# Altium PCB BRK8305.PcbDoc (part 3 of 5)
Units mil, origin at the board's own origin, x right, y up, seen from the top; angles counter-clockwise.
Board outline 5944.89 x 4139.76 mil, 4 copper layers (L1-Top, L2-GND, L3-GND, L4-BOT), stack 61.2 mil thick; 237 components, 286 nets, 1257 pads, 698 vias.
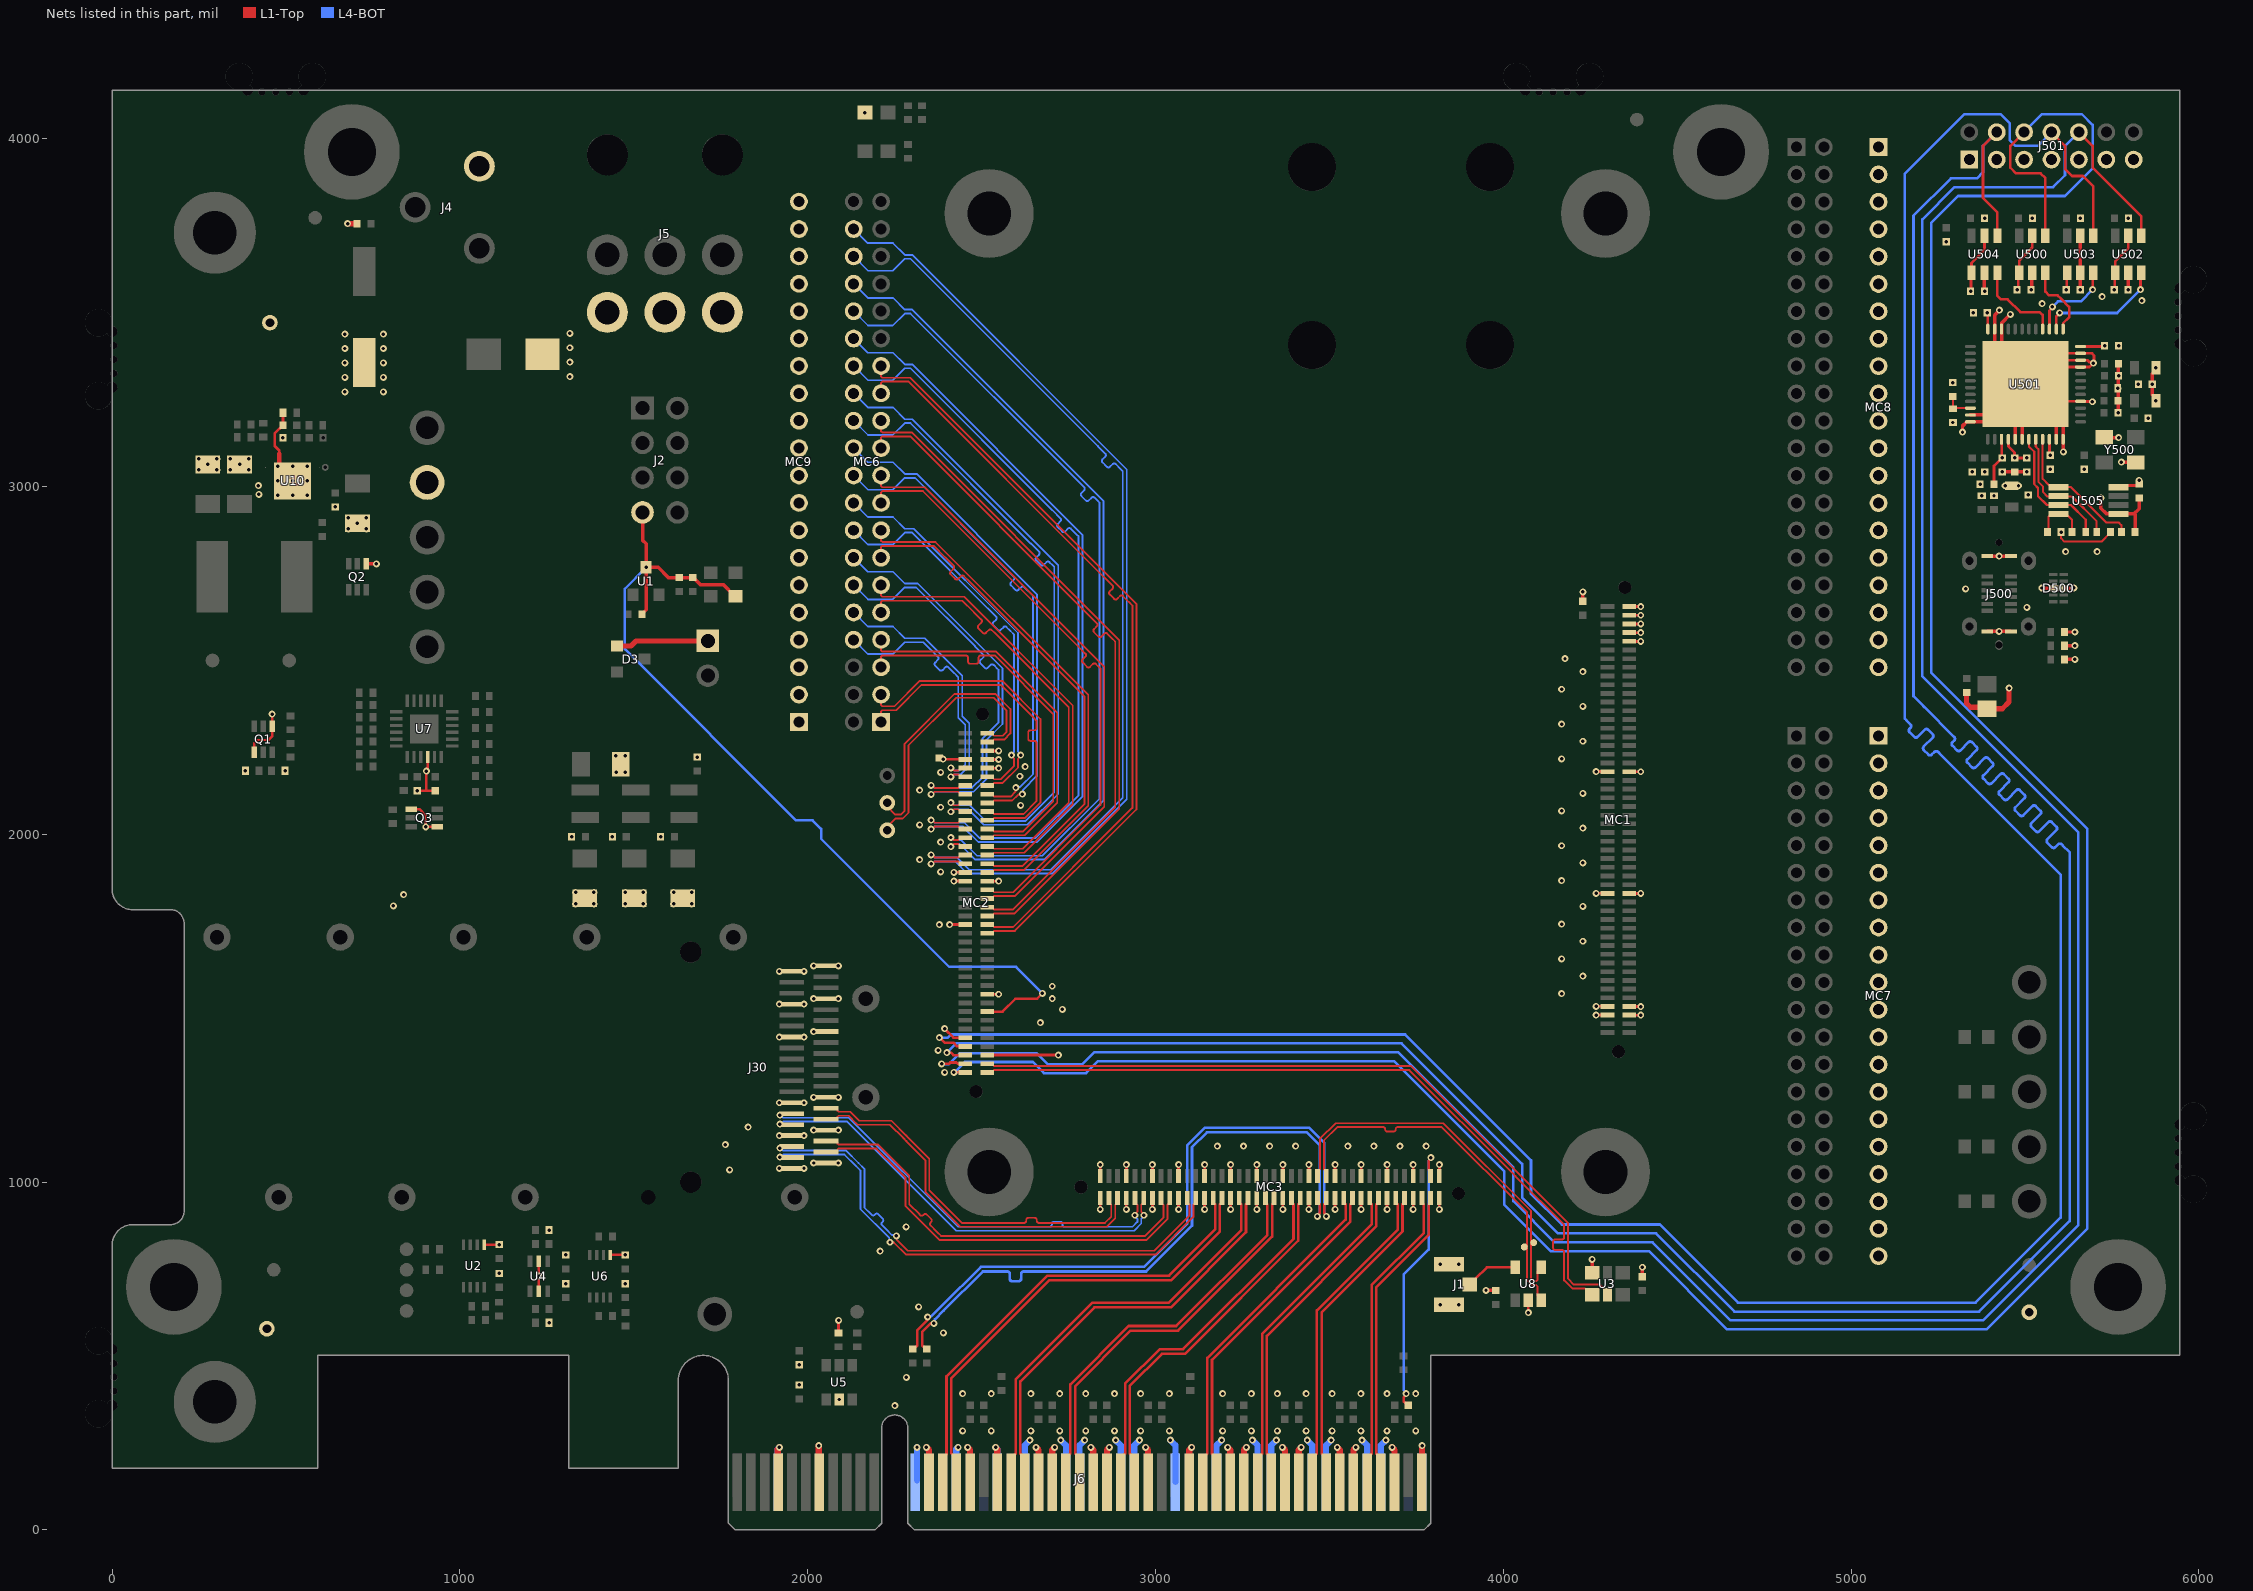
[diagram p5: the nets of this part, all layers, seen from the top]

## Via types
v1: diameter 20, hole 10, L1-Top to L4-BOT, tented both sides, 698 vias

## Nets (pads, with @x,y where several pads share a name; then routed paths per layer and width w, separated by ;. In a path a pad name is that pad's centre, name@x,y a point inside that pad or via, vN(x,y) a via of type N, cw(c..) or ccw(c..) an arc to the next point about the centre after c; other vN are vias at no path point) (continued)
B85_L10N: MC2.36 MC6.25 | length 2202.8
  L1-Top w5.25: MC6.25@2210.82,3268.11 2210.82,3298.78 2213.89,3301.86 2289.75,3301.86 2853.01,2738.6 2854.86,2736.74 2876.25,2715.35 cw(c2871.98,2711.07) 2876.25,2706.79 2867.96,2698.5 ccw(c2872.23,2694.22) 2867.96,2689.94 2880.79,2677.11 ccw(c2885.07,2681.39) 2889.35,2677.11 2897.64,2685.4 cw(c2901.92,2681.13) 2906.2,2685.4 2923.61,2668 2925.46,2666.14 2933.42,2658.18 2933.42,2076.24 2590.85,1733.68 2535.42,1733.68 2528.54,1740.55 MC2.36@2515.75,1740.55
B85_L10P: MC2.34 MC6.27 | length 2202.8
  L1-Top w5.25: MC6.27@2210.82,3346.85 2210.82,3316.18 2213.89,3313.11 2294.41,3313.11 2941.37,2666.14 2944.67,2662.84 2944.67,2071.58 2595.51,1722.43 2535.42,1722.43 2528.54,1715.55 MC2.34@2515.75,1715.55
B85_L11N: MC2.40 MC6.21 | length 1956.2
  L1-Top w5.25: MC6.21@2210.82,3110.63 2210.82,3141.3 2213.89,3144.37 2294.03,3144.37 2808.04,2630.37 2809.89,2628.51 2831.28,2607.12 cw(c2827,2602.85) 2831.28,2598.57 2822.99,2590.27 ccw(c2827.26,2585.99) 2822.99,2581.72 2835.82,2568.88 ccw(c2840.1,2573.16) 2844.38,2568.88 2852.67,2577.18 cw(c2856.95,2572.9) 2861.23,2577.18 2877.1,2561.3 2878.96,2559.45 2884.26,2554.14 2884.26,2078.59 2589.35,1783.68 2535.42,1783.68 2528.54,1790.55 MC2.40@2515.75,1790.55
B85_L11P: MC2.38 MC6.23 | length 1956.2
  L1-Top w5.25: MC6.23@2210.82,3189.37 2210.82,3158.7 2213.89,3155.62 2298.69,3155.62 2895.51,2558.8 2895.51,2073.93 2594.01,1772.43 2535.42,1772.43 2528.54,1765.55 MC2.38@2515.75,1765.55
B85_L12N: MC2.44 MC6.17 | length 1735.7
  L1-Top w5.25: MC6.17@2210.82,2953.15 2210.82,2983.82 2213.89,2986.89 2218.55,2986.89 2331.35,2986.89 2775.1,2543.15 2776.96,2541.29 2798.35,2519.9 cw(c2794.07,2515.62) 2798.35,2511.34 2790.05,2503.05 ccw(c2794.33,2498.77) 2790.05,2494.49 2802.89,2481.66 ccw(c2807.17,2485.93) 2811.44,2481.66 2819.74,2489.95 cw(c2824.02,2485.67) 2828.3,2489.95 2834.79,2483.46 2836.65,2481.6 2841.31,2476.94 2841.31,2084.42 2590.56,1833.68 2535.42,1833.68 2528.54,1840.55 MC2.44@2515.75,1840.55
B85_L12P: MC2.42 MC6.19 | length 1735.7
  L1-Top w5.25: MC6.19@2210.82,3031.89 2210.82,3001.22 2213.89,2998.14 2336.01,2998.14 2852.56,2481.6 2852.56,2079.76 2595.22,1822.43 2535.42,1822.43 2528.54,1815.55 MC2.42@2515.75,1815.55
B86_L1N: MC2.71 MC6.8 | length 768.7
  L1-Top w5.25: v1(2411.42,2191.05) 2412.87,2191.05 2420.24,2183.68 2433.09,2183.68 2439.96,2190.55 MC2.71@2452.76,2190.55
  L4-BOT w5.25: MC6.8@2132.08,2559.45 2173.18,2518.35 2244.52,2518.35 2278.85,2552.67 2332.19,2552.67 2351.02,2533.84 2352.88,2531.99 2374.27,2510.6 cw(c2369.99,2506.32) 2374.27,2502.04 2366.14,2493.91 ccw(c2370.42,2489.63) 2366.14,2485.36 2378.98,2472.52 ccw(c2383.26,2476.8) 2387.53,2472.52 2395.66,2480.65 cw(c2399.94,2476.37) 2404.22,2480.65 2418.54,2466.33 2420.4,2464.47 2432.79,2452.08 2432.79,2334.81 2452.76,2314.84 2452.76,2200.79 2435.64,2183.68 2421.87,2183.68 2414.49,2191.05 v1(2411.42,2191.05)
B86_L1P: MC2.69 MC6.10 | length 768.7
  L1-Top w5.25: v1(2411.42,2165.05) 2412.87,2165.05 2420.24,2172.43 2433.09,2172.43 2439.96,2165.55 MC2.69@2452.76,2165.55
  L4-BOT w5.25: MC6.10@2132.08,2638.19 2172.62,2597.65 2245.06,2597.65 2278.79,2563.92 2336.85,2563.92 2369.86,2530.92 2444.04,2456.74 2444.04,2339.47 2464.01,2319.5 2464.01,2196.13 2440.3,2172.43 2421.87,2172.43 2414.49,2165.05 v1(2411.42,2165.05)
B86_L2N: MC2.67 MC6.12 | length 1178.7
  L1-Top w5.25: v1(2354.33,2141.05) 2357.41,2141.05 2364.78,2133.68 2433.09,2133.68 2439.96,2140.55 MC2.67@2452.76,2140.55
  L4-BOT w5.25: MC6.12@2132.08,2716.93 2173.18,2675.83 2244.52,2675.83 2278.85,2710.15 2311.21,2710.15 2481,2540.36 2482.86,2538.5 2504.25,2517.11 cw(c2499.97,2512.83) 2504.25,2508.56 2496.12,2500.43 ccw(c2500.4,2496.15) 2496.12,2491.87 2508.96,2479.04 ccw(c2513.23,2483.32) 2517.51,2479.04 2525.64,2487.17 cw(c2529.92,2482.89) 2534.19,2487.17 2542.95,2478.41 2544.81,2476.55 2548.61,2472.76 2548.61,2322.06 2502.76,2276.21 2502.76,2164.58 2471.85,2133.68 2364.78,2133.68 2357.41,2141.05 v1(2354.33,2141.05)
B86_L2P: MC2.65 MC6.14 | length 1178.7
  L1-Top w5.25: v1(2354.33,2115.05) 2357.41,2115.05 2364.78,2122.43 2433.09,2122.43 2439.96,2115.55 MC2.65@2452.76,2115.55
  L4-BOT w5.25: MC6.14@2132.08,2795.67 2172.62,2755.13 2245.06,2755.13 2278.79,2721.4 2315.87,2721.4 2559.86,2477.42 2559.86,2317.4 2514.01,2271.55 2514.01,2159.92 2476.51,2122.43 2364.78,2122.43 2357.41,2115.05 v1(2354.33,2115.05)
B86_L3N: MC2.63 MC6.24 | length 1864.4
  L1-Top w5.25: v1(2411.42,2091.05) 2412.87,2091.05 2420.24,2083.68 2433.09,2083.68 2439.96,2090.55 MC2.63@2452.76,2090.55
  L4-BOT w5.25: MC6.24@2132.08,3189.37 2173.18,3148.27 2244.52,3148.27 2278.85,3182.59 2295.28,3182.59 2641.69,2836.18 2643.55,2834.32 2664.94,2812.93 cw(c2660.66,2808.66) 2664.94,2804.38 2656.81,2796.25 ccw(c2661.09,2791.97) 2656.81,2787.7 2669.64,2774.86 ccw(c2673.92,2779.14) 2678.2,2774.86 2686.33,2782.99 cw(c2690.6,2778.71) 2694.88,2782.99 2702.15,2775.73 2704,2773.87 2708.66,2769.21 2708.66,2120.71 2626.77,2038.82 2510.96,2038.82 2466.1,2083.68 2421.87,2083.68 2414.49,2091.05 v1(2411.42,2091.05)
B86_L3P: MC2.61 MC6.26 | length 1864.4
  L1-Top w5.25: v1(2411.42,2065.05) 2412.87,2065.05 2420.24,2072.43 2433.09,2072.43 2439.96,2065.55 MC2.61@2452.76,2065.55
  L4-BOT w5.25: MC6.26@2132.08,3268.11 2172.62,3227.57 2245.06,3227.57 2278.79,3193.84 2299.94,3193.84 2719.91,2773.87 2719.91,2116.05 2631.43,2027.57 2506.3,2027.57 2461.44,2072.43 2421.87,2072.43 2414.49,2065.05 v1(2411.42,2065.05)
B86_L4N: MC2.59 MC6.28 | length 2259.5
  L1-Top w5.25: v1(2354.33,2041.05) 2357.41,2041.05 2364.78,2033.68 2433.09,2033.68 2439.96,2040.55 MC2.59@2452.76,2040.55
  L4-BOT w5.25: MC6.28@2132.08,3346.85 2173.18,3305.75 2244.52,3305.75 2278.85,3340.08 2295.28,3340.08 2703.17,2932.18 2705.02,2930.33 2726.41,2908.94 cw(c2722.14,2904.66) 2726.41,2900.38 2718.29,2892.25 ccw(c2722.56,2887.98) 2718.29,2883.7 2731.12,2870.86 ccw(c2735.4,2875.14) 2739.68,2870.86 2747.8,2878.99 cw(c2752.08,2874.71) 2756.36,2878.99 2771.97,2863.38 2773.82,2861.53 2778.48,2856.87 2778.48,2113.13 2654.66,1989.3 2494.88,1989.3 2450.5,2033.68 2364.78,2033.68 2357.41,2041.05 v1(2354.33,2041.05)
B86_L4P: MC2.57 MC6.30 | length 2259.5
  L1-Top w5.25: v1(2354.33,2015.05) 2357.41,2015.05 2364.78,2022.43 2433.09,2022.43 2439.96,2015.55 MC2.57@2452.76,2015.55
  L4-BOT w5.25: MC6.30@2132.08,3425.59 2172.62,3385.05 2245.06,3385.05 2278.79,3351.33 2299.94,3351.33 2789.73,2861.53 2789.73,2108.47 2659.32,1978.05 2490.22,1978.05 2445.84,2022.43 2364.78,2022.43 2357.41,2015.05 v1(2354.33,2015.05)
B86_L5N_HDGC: MC2.55 MC6.32 | length 2415.5
  L1-Top w5.25: v1(2411.42,1991.05) 2412.87,1991.05 2420.24,1983.68 2433.09,1983.68 2439.96,1990.55 MC2.55@2452.76,1990.55
  L4-BOT w5.25: MC6.32@2132.08,3504.33 2173.18,3463.23 2244.52,3463.23 2278.85,3497.56 2295.28,3497.56 2771.45,3021.39 2773.3,3019.53 2794.69,2998.14 cw(c2790.41,2993.86) 2794.69,2989.58 2786.57,2981.46 ccw(c2790.84,2977.18) 2786.57,2972.9 2799.4,2960.07 ccw(c2803.68,2964.34) 2807.96,2960.07 2816.08,2968.19 cw(c2820.36,2963.91) 2824.64,2968.19 2832.61,2960.22 2834.46,2958.37 2839.12,2953.71 2839.12,2103.18 2674.76,1938.82 2486.51,1938.82 2441.65,1983.68 2421.87,1983.68 2414.49,1991.05 v1(2411.42,1991.05)
B86_L5P_HDGC: MC2.53 MC6.34 | length 2415.5
  L1-Top w5.25: v1(2411.42,1965.05) 2412.87,1965.05 2420.24,1972.43 2433.09,1972.43 2439.96,1965.55 MC2.53@2452.76,1965.55
  L4-BOT w5.25: MC6.34@2132.08,3583.07 2172.62,3542.53 2245.06,3542.53 2278.79,3508.81 2299.94,3508.81 2850.37,2958.37 2850.37,2098.52 2679.42,1927.57 2481.85,1927.57 2436.99,1972.43 2421.87,1972.43 2414.49,1965.05 v1(2411.42,1965.05)
B86_L6N_HDGC: MC2.51 MC6.36 | length 2792.7
  L1-Top w5.25: v1(2354.33,1941.05) 2357.41,1941.05 2364.78,1933.68 2433.09,1933.68 2439.96,1940.55 MC2.51@2452.76,1940.55
  L4-BOT w5.25: MC6.36@2132.08,3661.81 2173.18,3620.71 2244.52,3620.71 2278.85,3655.04 2295.28,3655.04 2832.16,3118.15 2834.02,3116.3 2855.41,3094.9 cw(c2851.13,3090.63) 2855.41,3086.35 2847.28,3078.22 ccw(c2851.56,3073.94) 2847.28,3069.67 2860.11,3056.83 ccw(c2864.39,3061.11) 2868.67,3056.83 2876.8,3064.96 cw(c2881.07,3060.68) 2885.35,3064.96 2898.47,3051.84 2900.33,3049.98 2905.83,3044.48 2905.83,2105.98 2698.21,1898.37 2463.87,1898.37 2428.56,1933.68 2364.78,1933.68 2357.41,1941.05 v1(2354.33,1941.05)
B86_L6P_HDGC: MC2.49 MC6.38 | length 2792.7
  L1-Top w5.25: v1(2354.33,1915.05) 2357.41,1915.05 2364.78,1922.43 2433.09,1922.43 2439.96,1915.55 MC2.49@2452.76,1915.55
  L4-BOT w5.25: MC6.38@2132.08,3740.55 2172.62,3700.01 2245.06,3700.01 2278.79,3666.29 2299.94,3666.29 2917.08,3049.14 2917.08,2101.32 2702.87,1887.12 2459.21,1887.12 2423.9,1922.43 2364.78,1922.43 2357.41,1915.05 v1(2354.33,1915.05)
B86_L7N_HDGC: MC2.70 MC6.16 | length 1130.2
  L1-Top w5.25: MC2.70@2515.75,2165.55 2528.54,2165.55 2535.42,2158.68 2554.95,2158.68 2593.09,2196.82 2593.09,2217.26 2585.72,2224.63 v1(2585.72,2227.73)
  L4-BOT w5.25: MC6.16@2132.08,2874.41 2173.18,2833.31 2244.52,2833.31 2278.85,2867.63 2299.91,2867.63 2518.19,2649.35 2520.05,2647.5 2541.44,2626.11 cw(c2537.16,2621.83) 2541.44,2617.55 2533.31,2609.42 ccw(c2537.59,2605.15) 2533.31,2600.87 2546.15,2588.03 ccw(c2550.42,2592.31) 2554.7,2588.03 2562.83,2596.16 cw(c2567.11,2591.88) 2571.39,2596.16 2580.98,2586.56 2582.84,2584.7 2593.09,2574.45 2593.09,2238.18 2585.72,2230.81 v1(2585.72,2227.73)
B86_L7P_HDGC: MC2.68 MC6.18 | length 1130.2
  L1-Top w5.25: MC2.68@2515.75,2140.55 2528.54,2140.55 2535.42,2147.43 2559.6,2147.43 2604.34,2192.16 2604.34,2217.26 2611.72,2224.63 v1(2611.72,2227.73)
  L4-BOT w5.25: MC6.18@2132.08,2953.15 2172.62,2912.61 2245.06,2912.61 2278.79,2878.88 2304.57,2878.88 2604.34,2579.11 2604.34,2238.18 2611.72,2230.81 v1(2611.72,2227.73)
B86_L8N_HDGC: MC2.66 MC6.20 | length 1404.4
  L1-Top w5.25: MC2.66@2515.75,2115.55 2528.54,2115.55 2535.42,2108.68 2583.32,2108.68 2597.08,2122.44 2597.08,2132.87 v1(2598.41,2134.2)
  L4-BOT w5.25: MC6.20@2132.08,3031.89 2173.18,2990.79 2244.52,2990.79 2278.85,3025.11 2308.34,3025.11 2569.09,2764.36 2570.94,2762.51 2592.33,2741.12 cw(c2588.06,2736.84) 2592.33,2732.56 2584.21,2724.43 ccw(c2588.49,2720.15) 2584.21,2715.88 2597.04,2703.04 ccw(c2601.32,2707.32) 2605.6,2703.04 2613.72,2711.17 cw(c2618,2706.89) 2622.28,2711.17 2632.76,2700.69 2634.62,2698.83 2647.52,2685.93 2647.52,2172.88 2611.02,2136.37 2600.59,2136.37 v1(2598.41,2134.2)
B86_L8P_HDGC: MC2.64 MC6.22 | length 1404.4
  L1-Top w5.25: MC2.64@2515.75,2090.55 2528.54,2090.55 2535.42,2097.43 2587.98,2097.43 2605.04,2114.49 2615.47,2114.49 v1(2616.8,2115.81)
  L4-BOT w5.25: MC6.22@2132.08,3110.63 2172.62,3070.09 2245.06,3070.09 2278.79,3036.36 2312.99,3036.36 2658.77,2690.59 2658.77,2168.22 2618.97,2128.42 2618.97,2117.99 v1(2616.8,2115.81)
B86_L9N: MC2.62 MC6.1 | length 980
  L1-Top w5.25: MC6.1@2210.82,2323.23 2210.82,2353.9 2213.89,2356.97 2253.99,2356.97 2326.93,2429.92 2554.68,2429.92 2649.49,2335.11 2657.48,2327.12 2657.48,2305.26 cw(c2651.43,2305.26) 2651.43,2299.21 2639.7,2299.21 ccw(c2639.7,2293.16) 2633.65,2293.16 2633.65,2275.01 ccw(c2639.7,2275.01) 2639.7,2268.96 2651.43,2268.96 cw(c2651.43,2262.91) 2657.48,2262.91 2657.48,2233.66 2657.48,2095.76 2620.4,2058.68 2535.42,2058.68 2528.54,2065.55 MC2.62@2515.75,2065.55
B86_L9P: MC2.60 MC6.3 | length 980
  L1-Top w5.25: MC6.3@2210.82,2401.97 2210.82,2371.3 2213.89,2368.22 2249.33,2368.22 2322.27,2441.17 2559.34,2441.17 2668.73,2331.78 2668.73,2091.1 2625.06,2047.43 2535.42,2047.43 2528.54,2040.55 MC2.60@2515.75,2040.55
B86_L10N: MC2.58 MC6.5 | length 1113.3
  L1-Top w5.25: MC6.5@2210.82,2480.71 2210.82,2511.38 2213.89,2514.45 2421.85,2514.45 2454.73,2514.45 cw(c2454.73,2508.4) 2460.78,2508.4 2460.78,2496.67 ccw(c2466.83,2496.67) 2466.83,2490.62 2484.98,2490.62 ccw(c2484.98,2496.67) 2491.03,2496.67 2491.03,2508.4 cw(c2497.08,2508.4) 2497.08,2514.45 2526.36,2514.45 2537.02,2514.45 2705.79,2345.68 2705.79,2095.28 2619.19,2008.68 2535.42,2008.68 2528.54,2015.55 MC2.58@2515.75,2015.55
B86_L10P: MC2.56 MC6.7 | length 1113.3
  L1-Top w5.25: MC6.7@2210.82,2559.45 2210.82,2528.78 2213.89,2525.7 2541.68,2525.7 2717.04,2350.34 2717.04,2090.62 2623.85,1997.43 2535.42,1997.43 2528.54,1990.55 MC2.56@2515.75,1990.55
B86_L11N: MC2.54 MC6.9 | length 1303
  L1-Top w5.25: MC6.9@2210.82,2638.19 2210.82,2668.86 2213.89,2671.93 2444.62,2671.93 2475.78,2640.77 2477.63,2638.92 2499.02,2617.53 cw(c2494.75,2613.25) 2499.02,2608.97 2490.73,2600.68 ccw(c2495.01,2596.4) 2490.73,2592.12 2503.56,2579.29 ccw(c2507.84,2583.56) 2512.12,2579.29 2520.41,2587.58 cw(c2524.69,2583.3) 2528.97,2587.58 2539.82,2576.73 2541.68,2574.87 2750.56,2365.99 2750.56,2091.26 2617.98,1958.68 2535.42,1958.68 2528.54,1965.55 MC2.54@2515.75,1965.55
B86_L11P: MC2.52 MC6.11 | length 1303
  L1-Top w5.25: MC6.11@2210.82,2716.93 2210.82,2686.26 2213.89,2683.18 2449.28,2683.18 2761.81,2370.65 2761.81,2086.6 2622.64,1947.43 2535.42,1947.43 2528.54,1940.55 MC2.52@2515.75,1940.55
B86_L12N: MC2.50 MC6.13 | length 1498.6
  L1-Top w5.25: MC6.13@2210.82,2795.67 2210.82,2826.34 2213.89,2829.41 2362.45,2829.41 2395.96,2795.91 2397.81,2794.05 2419.2,2772.66 cw(c2414.92,2768.38) 2419.2,2764.1 2410.91,2755.81 ccw(c2415.18,2751.53) 2410.91,2747.25 2423.74,2734.42 ccw(c2428.02,2738.69) 2432.3,2734.42 2440.59,2742.71 cw(c2444.87,2738.43) 2449.15,2742.71 2458.92,2732.94 2460.78,2731.08 2795.19,2396.67 2795.19,2087.1 2616.77,1908.68 2535.42,1908.68 2528.54,1915.55 MC2.50@2515.75,1915.55
B86_L12P: MC2.48 MC6.15 | length 1498.6
  L1-Top w5.25: MC6.15@2210.82,2874.41 2210.82,2843.74 2213.89,2840.66 2367.11,2840.66 2806.44,2401.33 2806.44,2082.44 2621.43,1897.43 2535.42,1897.43 2528.54,1890.55 MC2.48@2515.75,1890.55
DGND: C5.2 C6.1 C9.1 C10.1 C11.1 C12.1 C27.1 C28.1 C31.1 C32.1 C33.1 C34.1 C35.1 C36.1 C37.1 C38.1 C47.1 C48.1 C49.1 C50.1 C55.1 C56.1 C90.1 C91.1 C92.1 C93.1 C94.1 C95.1 C111.1 C112.1 C500.1 C501.1 C502.1 C503.1 C504.1 C505.1 C506.1 C507.1 C508.1 C509.1 C510.1 C511.1 C512.1 C513.1 C514.1 C515.1 C516.1 C517.1 C518.1 C519.1 C520.1 C521.1 C522.1 C523.1 C524.1 C525.1 C526.1 C527.1 C528.1 D2.1 D3.1 D4.1 D500.3 D500.8 FB503.2 J1.2 J3.1 J4.2 J5.4 J5.5 J5.6 J6.A4 J6.A12 J6.A15 J6.A18 J6.A20 J6.A23 J6.A24 J6.A27 J6.A28 J6.A31 J6.A34 J6.A37 J6.A38 J6.A41 J6.A42 J6.A45 J6.A46 J6.A49 J6.B4 J6.B7 J6.B13 J6.B16 J6.B18 J6.B21 J6.B22 J6.B25 J6.B26 J6.B29 J6.B32 J6.B35 J6.B36 J6.B39 J6.B40 J6.B43 J6.B44 J6.B47 J6.B49 J30.1 J30.4 J30.7 J30.13 J30.16 J30.19 J30.20 J30.23 J30.26 J30.32 J30.35 J30.38 J500.A1 J500.A12 J500.B1 J500.B12 J501.1 J501.3 J501.5 J501.7 J501.9 J501.11 J501.13 MC1.5 MC1.6 MC1.7 MC1.8 MC1.33 MC1.34 MC1.61 MC1.62 MC1.92 MC1.94 MC1.96 MC1.98 MC1.100 MC2.6 MC2.9 MC2.20 MC2.35 MC2.45 MC2.46 MC2.47 MC2.72 MC2.73 MC2.74 MC2.76 MC3.1 MC3.2 MC3.7 MC3.8 MC3.13 MC3.14 MC3.19 MC3.20 MC3.25 MC3.26 MC3.31 MC3.32 MC3.37 MC3.38 MC3.43 MC3.44 MC3.49 MC3.50 MC3.55 MC3.56 MC3.61 MC3.62 MC3.67 MC3.68 MC3.73 MC3.74 MC3.79 MC3.80 MC7.1 MC7.2 MC7.3 MC7.4 MC7.5 MC7.6 MC7.7 MC7.8 MC7.9 MC7.10 MC7.11 MC7.12 MC7.13 MC7.14 MC7.15 MC7.16 MC7.17 MC7.18 MC7.19 MC7.20 MC8.1 MC8.2 MC8.3 MC8.4 MC8.5 MC8.6 MC8.7 MC8.8 MC8.9 MC8.10 MC8.11 MC8.12 MC8.13 MC8.14 MC8.15 MC8.16 MC8.17 MC8.18 MC8.19 MC8.20 MC9.1 MC9.2 MC9.3 MC9.4 MC9.5 MC9.6 MC9.7 MC9.8 MC9.9 MC9.10 MC9.11 MC9.12 MC9.13 MC9.14 MC9.15 MC9.16 MC9.17 MC9.18 MC9.19 MC9.20 Q1.1 Q1.4 Q2.1 Q3.1 Q3.4 R12.1 R22.1 R24.1 R32.1 R33.1 R78.1 R500.1 R501.2 R502.1 R504.2 R505.2 R506.2 R508.1 TP26.1 TP27.1 TP28.1 TP29.1 U2.1 U3.3 U4.2 U4.5 U5.2 U6.1 U7.22 U8.2 U10.4 U10.7 U10.8 U10.PAD U500.2 U501.4 U501.9 U501.10 U501.11 U501.22 U501.23 U501.35 U501.36 U501.41 U501.42 U501.47 U501.48 U501.PAD U502.2 U503.2 U503.5 U504.2 U505.5 Y500.2 Y500.4 | length 10656.6
  L1-Top w7: Q1.1@408.56,2235.89 408.56,2261.89 418,2271.33 449.39,2271.33 459.74,2281.68 Q1.4@459.74,2310.7 v1(459.74,2346.12) ; Q3.1@859.84,2072.83 883.33,2072.83 901.57,2054.59 v1(901.57,2021.65) Q3.4@934.65,2021.65 ; U2.1@1069.18,820.3 1069.57,820.7 v1(1112.49,820.7) ; U4.5@1226.66,686.44 U4.2@1226.66,773.06 ; U6.1@1432.37,790.78 v1(1475.67,790.78)
  L1-Top w8: U10.4@480.28,3094.41 480.28,3104.25 467.15,3117.38 467.15,3152.69 C55.1@490.68,3176.22 C55.1@491.07,3176.61 ; C55.1@491.47,3177.01 R78.1@491.47,3212.61 ; v1(877.56,2125.59) 903.15,2125.59 ; v1@902.69,2181.79 905.41,2184.51 905.41,2190.3 907.09,2191.98 U7.22@907.09,2222.44 ; v1(903.11,2182.21) 903.15,2125.59 ; C35.1@928.74,2125.59 903.15,2125.59 ; R24.1@2088.57,566.14 v1(2088.57,602.6) ; v1(2389.02,2216.51) 2389.57,2215.96 MC2.73@2452.81,2215.96 ; v1(2393.21,1441.73) 2393.21,1441.22 2418.88,1415.55 MC2.9@2452.4,1415.55 ; v1(2407.6,1740.55) MC2.35@2452.4,1740.55 ; v1@2420.26,1865.96 MC2.45@2452.81,1865.96 ; v1@2420.26,1890.96 MC2.47@2452.81,1890.96 ; MC2.20@2515.69,1540.14 v1@2548.24,1540.14 ; MC2.46@2515.69,1865.14 v1@2548.24,1865.14 ; MC2.72@2515.69,2190.14 v1@2548.24,2190.14 ; MC2.74@2515.69,2215.14 v1@2548.24,2215.14 ; MC2.76@2515.69,2240.14 v1@2548.24,2240.14 ; MC2.6@2516.1,1365.55 v1(2720.46,1365.55) ; v1@2840.75,922.18 MC3.2@2840.75,954.72 ; MC3.1@2841.16,1017.66 v1@2841.16,1050.21 ; v1@2915.75,922.18 MC3.8@2915.75,954.72 ; MC3.7@2916.16,1017.66 v1@2916.16,1050.21 ; v1@2990.75,922.18 MC3.14@2990.75,954.72 ; MC3.13@2991.16,1017.66 v1@2991.16,1050.21 ; v1@3065.75,922.18 MC3.20@3065.75,954.72 ; MC3.19@3066.16,1017.66 v1@3066.16,1050.21 ; v1@3140.75,922.18 MC3.26@3140.75,954.72 ; MC3.25@3141.16,1017.66 v1@3141.16,1050.21 ; v1@3215.75,922.18 MC3.32@3215.75,954.72 ; MC3.31@3216.16,1017.66 v1@3216.16,1050.21 ; v1@3290.75,922.18 MC3.38@3290.75,954.72 ; MC3.37@3291.16,1017.66 v1@3291.16,1050.21 ; v1@3365.75,922.18 MC3.44@3365.75,954.72 ; MC3.43@3366.16,1017.66 v1@3366.16,1050.21 ; v1@3440.75,922.18 MC3.50@3440.75,954.72 ; MC3.49@3441.16,1017.66 v1@3441.16,1050.21 ; v1@3515.75,922.18 MC3.56@3515.75,954.72 ; MC3.55@3516.16,1017.66 v1@3516.16,1050.21 ; v1@3590.75,922.18 MC3.62@3590.75,954.72 ; MC3.61@3591.16,1017.66 v1@3591.16,1050.21 ; v1@3665.75,922.18 MC3.68@3665.75,954.72 ; MC3.67@3666.16,1017.66 v1@3666.16,1050.21 ; v1@3740.54,922.2 MC3.74@3740.54,954.75 ; MC3.73@3740.95,1017.69 v1@3740.95,1050.24 ; v1@3815.54,922.2 MC3.80@3815.54,954.75 ; MC3.79@3815.95,1017.69 v1@3815.95,1050.24 ; v1(4071.56,625.31) 4071.56,660.6 U8.2@4071.91,660.95 ; v1@4266.72,1480.71 MC1.5@4299.27,1480.71 ; v1@4266.72,1505.71 MC1.7@4299.27,1505.71 ; v1@4266.72,1830.71 MC1.33@4299.27,1830.71 ; v1@4266.72,2180.71 MC1.61@4299.27,2180.71 ; MC1.6@4362.15,1479.9 v1@4394.7,1479.9 ; MC1.8@4362.15,1504.9 v1@4394.7,1504.9 ; MC1.34@4362.15,1829.9 v1@4394.7,1829.9 ; MC1.62@4362.15,2179.9 v1@4394.7,2179.9 ; MC1.92@4362.15,2554.9 v1@4394.7,2554.9 ; MC1.94@4362.15,2579.9 v1@4394.7,2579.9 ; MC1.96@4362.15,2604.9 v1@4394.7,2604.9 ; MC1.98@4362.15,2629.9 v1@4394.7,2629.9 ; MC1.100@4362.15,2654.9 v1@4394.7,2654.9 ; U501.PAD@5501.13,3294.49 U501.PAD@5550.35,3343.7 ; U501.PAD@5550.35,3245.28 U501.4@5659.6,3245.28 5659.95,3244.93 5692.58,3244.93 v1(5693.62,3243.88) ; U501.PAD@5550.35,3343.7 U501.PAD@5570.03,3363.39 ; U501.PAD@5550.35,3343.7 U501.9@5659.6,3343.7 5684.77,3343.7 v1(5696.2,3355.14) ; U501.PAD@5570.03,3363.39 5589.72,3383.07 U501.11@5659.6,3383.07 5692.08,3383.07 5697.98,3377.17 5697.98,3356.92 v1(5696.2,3355.14) ; U501.PAD@5570.03,3363.39 U501.10@5659.6,3363.39 5679.9,3363.39 5685.86,3357.43 5693.9,3357.43 v1(5696.2,3355.14)
  L1-Top w10: C55.1@491.07,3176.61 C55.1@491.47,3177.01 ; Q2.1@730.74,2778.01 v1(759.45,2778.01) ; v1(3950,688.76) 3950.2,688.96 3977.36,688.96 C37.1@3977.56,689.16 ; C38.1@4228.45,2670.26 v1(4228.45,2697.3) ; U3.3@4254.98,739.69 v1(4254.98,778.13) ; C33.1@4399.38,728.27 v1(4399.38,755.43) ; v1(5320.03,3156.7) 5320.03,3174.26 5332,3186.22 U501.36@5342.67,3186.22 5392.87,3186.22 U501.PAD@5408.61,3201.97 ; U501.35@5342.67,3205.91 5404.68,3205.91 U501.PAD@5408.61,3201.97 ; U504.2@5383.02,3615.36 5383.22,3615.16 5383.22,3562.41 v1(5383.42,3562.21) ; J500.B1@5391.09,2583.86 J500.A12@5459.2,2583.86 ; J500.B12@5391.09,2800.4 J500.A1@5459.2,2800.4 ; v1(5426.33,3507.09) 5412.55,3493.31 U501.23@5412.55,3452.96 5412.55,3383.07 U501.PAD@5432.24,3363.39 ; v1(5434.2,3042.13) C512.1@5469.64,3042.13 v1(5505.07,3042.13) ; v1(5457.83,3495.28) 5432.24,3469.69 U501.22@5432.24,3452.96 U501.PAD@5432.24,3363.39 ; U501.41@5471.61,3136.03 U501.PAD@5471.61,3264.96 ; U501.42@5491.29,3136.03 U501.PAD@5491.29,3284.65 ; v1(5517.27,3566.15) 5519.05,3567.92 5519.05,3613.59 U500.2@5520.82,3615.36 ; v1(5547.87,2708.45) 5548.1,2708.22 5581.5,2708.22 D500.3@5581.84,2707.88 ; U501.47@5589.72,3136.03 U501.PAD@5589.72,3205.91 ; v1(5610.05,3099.95) 5609.48,3100.51 5609.48,3135.95 U501.48@5609.4,3136.03 5609.4,3186.22 U501.PAD@5589.72,3205.91 ; D500.8@5611.86,2707.88 5612.16,2708.17 5639.76,2708.17 v1(5640.05,2708.47) ; R504.2@5613.34,2503.15 v1(5642.87,2503.15) ; R505.2@5613.34,2542.52 v1(5642.87,2542.52) ; R506.2@5613.34,2581.89 v1(5642.87,2581.89) ; v1(5658.61,3566.15) U503.2@5658.61,3615.36 U503.5@5658.61,3721.66 U503.5@5658.81,3721.85 ; C520.1@5658.81,3770.67 v1(5659.01,3770.87) ; v1(5717.95,2966.99) 5717.95,2937.53 5734.02,2921.46 U505.5@5768.85,2921.46 5813.14,2921.46 ; Y500.4@5727.51,3141.93 5728.5,3140.95 v1(5768.85,3140.95) ; v1(5767.27,3211.82) 5768.06,3212.6 5768.06,3352.76 C502.1@5768.85,3353.55 ; v1(5776.72,3070.08) 5817.08,3070.08 Y500.2@5818.06,3069.1 ; v1(5796.41,3566.15) U502.2@5796.41,3615.36 ; R508.1@5816.09,2869.3 5816.09,2918.51 5813.14,2921.46 ; C527.1@5827.9,2967.33 5827.9,2936.22 5813.14,2921.46 ; U501.PAD@5408.61,3201.97 U501.PAD@5471.61,3264.96 ; U501.PAD@5432.24,3363.39 U501.PAD@5501.13,3294.49 ; U501.PAD@5471.61,3264.96 U501.PAD@5491.29,3284.65 ; U501.PAD@5491.29,3284.65 U501.PAD@5501.13,3294.49 ; U501.PAD@5501.13,3294.49 5550.35,3245.28 U501.PAD@5589.72,3205.91
  L1-Top w13: v1(476.67,3058.65) 480.28,3062.27 U10.4@480.28,3094.41
  L1-Top w15: v1(677.17,3755.91) C6.1@704.33,3755.91 ; D3.1@1451.7,2541.42 1491.66,2541.42 1506.54,2556.3 J3.1@1712.55,2556.3 ; C522.1@5331.84,2408.27 5331.84,2377.17 5343.65,2365.36 5386.96,2365.36 FB503.2@5390.9,2361.42 5434.2,2361.42 5453.89,2381.11 v1(5453.89,2420.48)
  L1-Top w18: J6.B4@1913.38,137.79 1913.38,232.25 1918.38,237.25 v1(1918.38,237.79) ; J6.B7@2031.49,137.79 v1(2031.49,242.76) ; v1(2341.22,237.81) 2341.22,237.27 2348.42,230.07 J6.B13@2348.42,137.79 ; v1(2459.33,237.81) 2459.33,237.27 2466.53,230.07 J6.B16@2466.53,137.79 ; v1(2540.27,237.79) 2540.27,237.25 2545.05,232.47 2545.05,221.74 2545.27,221.52 J6.B18@2545.27,137.79 ; v1(2656.18,237.81) 2656.18,237.27 2663.38,230.07 J6.B21@2663.38,137.79 ; J6.B22@2702.75,137.79 2702.75,230.07 2709.95,237.27 v1(2709.95,237.81) ; v1(2813.66,237.81) 2813.66,237.27 2820.86,230.07 J6.B25@2820.86,137.79 ; J6.B26@2860.23,137.79 2860.23,230.07 2867.43,237.27 v1(2867.43,237.81) ; v1(2971.14,237.81) 2971.14,237.27 2978.34,230.07 J6.B29@2978.34,137.79 ; J6.B32@3096.45,137.79 3096.45,230.07 3103.65,237.27 v1(3103.65,237.81) ; v1(3207.36,237.81) 3207.36,237.27 3214.56,230.07 J6.B35@3214.56,137.79 ; J6.B36@3253.93,137.79 3253.93,230.07 3261.13,237.27 v1(3261.13,237.81) ; v1(3364.84,237.81) 3364.84,237.27 3372.04,230.07 J6.B39@3372.04,137.79 ; J6.B40@3411.41,137.79 3411.41,230.07 3418.61,237.27 v1(3418.61,237.81) ; v1(3522.32,237.81) 3522.32,237.27 3529.52,230.07 J6.B43@3529.52,137.79 ; J6.B44@3568.89,137.79 3568.89,230.07 3576.09,237.27 v1(3576.09,237.81) ; v1(3679.8,237.81) 3679.8,237.27 3687,230.07 J6.B47@3687,137.79 ; J6.B49@3765.74,137.79 3765.96,138.01 3765.96,242.46 v1(3766.18,242.68)
  L4-BOT w18: J6.A4@1913.38,137.79 1913.38,232.79 v1(1918.38,237.79) ; J6.A12@2314.05,142.79 v1(2314.05,237.79) ; J6.A15@2427.16,137.79 2427.16,232.79 v1(2432.16,237.79) ; v1(2540.27,237.79) 2545.27,232.79 J6.A18@2545.27,137.79 ; J6.A20@2624.01,137.79 2624.01,243.81 v1(2638.76,258.56) ; v1(2727.36,258.56) 2742.12,243.81 J6.A23@2742.12,137.79 ; J6.A24@2781.49,137.79 2781.49,243.81 v1(2796.24,258.56) ; v1(2884.84,258.56) 2899.6,243.81 J6.A27@2899.6,137.79 ; J6.A28@2938.97,137.79 2938.97,243.81 v1(2953.72,258.56) ; v1(3042.32,258.56) 3057.08,243.81 J6.A31@3057.08,137.79 ; J6.A34@3175.19,137.79 3175.19,243.81 v1(3189.94,258.56) ; v1(3278.54,258.56) 3293.3,243.81 J6.A37@3293.3,137.79 ; J6.A38@3332.67,137.79 3332.67,243.81 v1(3347.42,258.56) ; v1(3436.03,258.56) 3450.78,243.81 J6.A41@3450.78,137.79 ; J6.A42@3490.15,137.79 3490.15,243.81 v1(3504.9,258.56) ; v1(3593.51,258.56) 3608.26,243.81 J6.A45@3608.26,137.79 ; J6.A46@3647.63,137.79 3647.63,243.81 v1(3662.38,258.56) ; J6.A49@3765.74,137.79 3765.96,138.01 3765.96,242.46 v1(3766.18,242.68)
  other v1: 2444.87,285.27 2527.55,285.27 2641.72,285.27 2724.4,285.27 2799.2,285.27 2881.88,285.27 2956.69,285.27 3039.36,285.27 3192.91,285.27 3275.58,285.27 3350.39,285.27 3433.06,285.27 3507.87,285.27 3590.54,285.27 3665.35,285.27 3748.02,285.27 2250.65,357.48 2090.54,375.2 2444.87,391.89 2527.55,391.89 2641.72,391.89 2724.4,391.89 2799.2,391.89 2881.88,391.89 2956.69,391.89 3039.36,391.89 3192.91,391.89 3275.58,391.89 3350.39,391.89 3433.06,391.89 3507.87,391.89 3590.54,391.89 3665.35,391.89 3748.02,391.89 1975.47,417.08 2283.67,439.01 1975.47,475.47 2389.76,566.93 1256.19,595.89 2318.9,641.73 3819.14,648.02 3871.85,648.02 1303.43,708.1 1475.67,708.1 1226.66,729.75 1112.49,738.02 3819.14,764.16 3871.85,764.16 1303.43,790.78 2208.19,801.67 1256.19,862.49 2282.51,871.78 2840.95,921.97 2915.95,921.97 2990.95,921.97 3065.95,921.97 3140.95,921.97 3215.95,921.97 3290.95,921.97 3365.95,921.97 3440.95,921.97 3515.95,921.97 3590.95,921.97 3665.95,921.97 3740.75,922 3815.75,922 1775.31,1035.47 1918.22,1039.41 1989.15,1039.41 2840.95,1050.41 2915.95,1050.41 2990.95,1050.41 3065.95,1050.41 3140.95,1050.41 3215.95,1050.41 3290.95,1050.41 3365.95,1050.41 3440.95,1050.41 3515.95,1050.41 3590.95,1050.41 3665.95,1050.41 3740.75,1050.44 3815.75,1050.44 2017.04,1055.16 2087.97,1055.16 3177.77,1103.92 3252.77,1103.92 3327.77,1103.92 3402.77,1103.92 3552.77,1103.92 3627.77,1103.92 3702.77,1103.92 3777.77,1103.92 1762.98,1108.03 1918.22,1133.9 1989.15,1133.9 2017.04,1149.65 2087.97,1149.65 1828.26,1158.5 1918.22,1228.39 1989.15,1228.39 2017.04,1244.13 2087.97,1244.13 2393.7,1315.55 2374.85,1378.98 1918.22,1417.36 1989.15,1417.36 2017.04,1433.11 2668.73,1458.66 4394.9,1480.1 4266.51,1480.51 2732.28,1497.08 4394.9,1505.1 4266.51,1505.51 1918.22,1511.85 1989.15,1511.85 2017.04,1527.6 2087.97,1527.6 2702.87,1527.6 2548.45,1540.35 4167.74,1542.32 2702.87,1563.35 4228.45,1592.8 1918.22,1606.34 1989.15,1606.34 2017.04,1622.09 2087.97,1622.09 4167.74,1642.32 4228.45,1692.8 2378.44,1740.55 4167.74,1742.32 4228.45,1792.8 808.35,1794.7 1332.71,1800.15 1384.71,1800.15 1475.43,1800.15 1527.43,1800.15 1614.21,1800.15 1666.21,1800.15 838.19,1826.65 4394.9,1830.1 4266.51,1830.51 1332.71,1833.07 1384.71,1833.07 1475.43,1833.07 1527.43,1833.07 1614.21,1833.07 1666.21,1833.07 2548.45,1865.35 2420.06,1865.76 4167.74,1867.32 2420.06,1890.76 2382,1892.05 4228.45,1917.8 2321.28,1927.57 4167.74,1967.32 2382,1978.05 1438.04,1993.4 1576.82,1993.4 1321.12,1993.76 4228.45,2017.8 2321.28,2027.57 4167.74,2067.32 2382,2078.05 2611.72,2083.66 4228.45,2117.8 2321.28,2127.57 2609.79,2167.12 1448.67,2178.44 1475.84,2178.44 2382,2178.05 4394.9,2180.1 4266.51,2180.51 382.97,2182.74 497.15,2182.74 2548.45,2190.35 2625.06,2195.04 2548.45,2215.35 4167.74,2217.32 1681.54,2222.14 1448.28,2225.68 1475.84,2225.68 2548.45,2240.35 4228.45,2267.8 4167.74,2317.32 4228.45,2367.8 4167.74,2417.32 4228.45,2467.8 4177.17,2505.3 4394.9,2555.1 4394.9,2580.1 5425.15,2583.86 4394.9,2605.1 4394.9,2630.1 5505.07,2652.76 4394.9,2655.1 5328.78,2705.75 5425.15,2800.4 5616.33,2813.19 5707.39,2813.19 679.15,2878.61 731.15,2878.61 705.15,2894.53 679.15,2910.44 731.15,2910.44 641.15,2941.53 5375.15,2973.63 5410.58,2973.63 476.67,2974.65 518.67,2974.65 560.67,2974.65 5509.01,2975.99 421.58,2977.49 420.28,3003.03 5370.82,3007.09 476.67,3016.65 518.67,3016.65 560.67,3016.65 5348.57,3042.13 5384.01,3042.13 249.15,3047.79 301.15,3047.79 340.15,3047.79 392.15,3047.79 5572,3050 5670.42,3050 518.67,3058.65 560.67,3058.65 275.15,3063.7 366.15,3063.7 249.15,3079.61 301.15,3079.61 340.15,3079.61 392.15,3079.61 491.07,3140.61 5853.89,3196.07 669.16,3272.45 779.76,3272.45 5766.49,3282.68 5825.54,3294.49 5292.47,3298.82 669.16,3313.98 779.76,3313.98 1315.75,3316.18 5768.85,3318.11 669.16,3355.51 779.76,3355.51 1315.75,3357.71 669.16,3397.04 779.76,3397.04 1315.75,3399.24 5768.85,3404.73 669.16,3438.57 779.76,3438.57 1315.75,3440.77 5351.13,3499.22 5549.12,3526.39 5835.78,3534.65 5721.61,3546.46 5272.79,3703.94 5383.42,3770.87 5521.21,3770.87 5796.8,3770.87 2164.33,4075.46
EECLK: R507.1 U501.44 U505.2 | length 382.1
  L1-Top w6: U501.44@5530.66,3136.03 5530.66,3115.24 5538.35,3107.55 5538.35,3013.45 5551.25,3000.54 5551.25,2984.66 5564.25,2971.66 U505.2@5594.64,2971.66 ; U505.2@5595.62,2972.64 U505.2@5594.64,2971.66 ; R507.1@5705.86,2869.3 5705.86,2900.79 5634.99,2971.66 U505.2@5594.64,2971.66
EECS: R508.2 U501.45 U505.1 | length 415.2
  L1-Top w6: U501.45@5550.35,3136.03 5550.35,3022.05 5567.79,3004.61 5589.24,3004.61 U505.1@5595.62,2998.23 5632.04,2998.23 5733.42,2896.85 5768.85,2896.85 5776.72,2888.98 R508.2@5776.72,2869.3
EEDATA: R509.1 U501.43 U505.3 | length 374.8
  L1-Top w6: U501.43@5510.98,3136.03 5510.98,3115.36 5526.25,3100.08 5526.25,3006.96 5537.25,2995.96 5537.25,2972.71 5562.91,2947.05 U505.3@5595.62,2947.05 5631.93,2947.05 5674.36,2904.62 R509.1@5674.36,2869.3
EEPROM_DO: R509.2 R510.1 U505.4 | length 158.5
  L1-Top w6: R510.1@5564.13,2869.3 5567.08,2872.25 5567.08,2912.6 5575.94,2921.46 U505.4@5595.62,2921.46 5601.48,2915.6 5624.12,2915.6 5634.99,2904.73 R509.2@5634.99,2869.3
FPGA_DXN: MC2.80 TP2.1 | length 759.2
  L1-Top w5.25: TP2.1@2228.35,2011.81 2228.35,2021.93 2251.97,2045.56 2272.35,2045.56 2289.53,2062.74 2289.53,2255.73 2426.51,2392.71 2534.57,2392.71 2571.46,2355.82 2571.46,2294.97 2560.17,2283.68 2535.42,2283.68 2528.54,2290.55 MC2.80@2515.75,2290.55
FPGA_DXP: MC2.78 TP1.1 | length 796.5
  L1-Top w5.25: TP1.1@2228.35,2090.55 2228.35,2080.43 2251.97,2056.81 2267.69,2056.81 2278.28,2067.4 2278.28,2260.39 2421.85,2403.96 2539.23,2403.96 2582.71,2360.48 2582.71,2290.31 2564.83,2272.43 2535.42,2272.43 2528.54,2265.55 MC2.78@2515.75,2265.55
FPGA_JTAG_TCK: J501.6 MC2.1 U500.4 | length 8186.7
  L1-Top w7.5: v1(2420.06,1315.55) MC2.1@2452.76,1315.55 ; J501.6@5497.2,4018.9 5457.83,3979.53 5457.83,3916.73 5474.07,3900.49 5544.63,3900.49 5558.22,3886.9 U500.4@5558.22,3721.66
  L4-BOT w7.5: v1@2420.06,1313.78 2451.74,1345.46 2647.52,1345.46 2679.2,1313.78 2799.87,1313.78 2834.26,1348.17 3686.1,1348.17 4003.01,1031.26 4003.01,934.83 4136.11,801.73 4418.13,801.73 4642.82,577.04 5388.98,577.04 5678.86,866.93 5678.86,2016.07 5230.04,2464.89 5230.04,3758.06 5307.48,3835.49 5614.74,3835.49 5694.19,3914.94 5694.19,4039.6 5662.92,4070.87 5549.16,4070.87 J501.6@5497.2,4018.9
FPGA_JTAG_TDI: J501.10 MC2.3 U502.4 | length 7922.1
  L1-Top w7.5: v1@2384.77,1340.55 2406.26,1340.55 2409.99,1344.28 2427.35,1344.28 2431.08,1340.55 MC2.3@2452.76,1340.55 ; J501.10@5654.68,4018.9 5694.05,3979.53 5694.05,3917.15 5833.81,3777.39 U502.4@5833.81,3721.66
  L4-BOT w7.5: v1(2384.5,1340.28) 2385.5,1339.28 2405.36,1339.28 2437.04,1370.96 2658.08,1370.96 2689.76,1339.28 2789.31,1339.28 2823.7,1373.67 3696.66,1373.67 4028.51,1041.82 4028.51,945.4 4146.67,827.23 4428.69,827.23 4653.39,602.54 5378.41,602.54 5653.36,877.49 5653.36,2005.5 5204.54,2454.32 5204.54,3768.62 5296.92,3860.99 5580.72,3860.99 5614.9,3895.18 5614.9,3979.13 J501.10@5654.68,4018.9
FPGA_JTAG_TDO: J501.8 MC2.7 U503.4 | length 8029.2
  L1-Top w7.5: v1(2378.62,1415.88) 2393.33,1401.16 2418.71,1401.16 2429.32,1390.55 MC2.7@2452.76,1390.55 ; J501.8@5575.94,4018.9 5615.31,3979.53 5615.31,3912.6 5634.99,3892.92 5666.49,3892.92 5696.01,3863.39 U503.4@5696.01,3721.66
  L4-BOT w7.5: v1@2378.91,1415.08 2401.74,1415.08 2411.33,1424.67 3717.79,1424.67 4079.51,1062.94 4079.51,966.52 4167.8,878.23 4449.82,878.23 4674.51,653.54 5357.29,653.54 5602.36,898.62 5602.36,1884.34 5252.49,2234.21 5249.84,2236.86 ccw(c5244.53,2231.56) 5239.23,2236.86 5231.45,2229.09 cw(c5226.86,2233.68) 5222.26,2229.09 5208.47,2242.88 cw(c5213.07,2247.47) 5208.47,2252.07 5234.63,2278.23 ccw(c5230.04,2282.83) 5234.63,2287.42 5220.85,2301.21 ccw(c5216.25,2296.62) 5211.65,2301.21 5190.66,2280.21 cw(c5186.06,2284.81) 5181.46,2280.21 5167.67,2294 cw(c5172.27,2298.6) 5167.67,2303.19 5170.29,2305.81 ccw(c5164.98,2311.11) 5170.29,2316.41 5161.08,2325.63 5158.43,2328.28 5153.54,2333.16 5153.54,3898.18 5326.23,4070.87 5429.83,4070.87 5456.2,4044.49 5456.2,3995.64 5472.31,3979.53 5536.57,3979.53 J501.8@5575.94,4018.9
FPGA_JTAG_TMS: J501.4 MC2.5 U504.4 | length 8141.7
  L1-Top w7.5: v1(2399.98,1372.31) 2400.11,1372.44 2411.37,1372.44 2418.76,1365.05 2452.26,1365.05 MC2.5@2452.76,1365.55 ; J501.4@5418.46,4018.9 5379.09,3979.53 5379.09,3829.93 5420.42,3788.59 U504.4@5420.42,3721.66
  L4-BOT w7.5: v1@2399.98,1372.52 2426.63,1399.17 3707.23,1399.17 4054.01,1052.38 4054.01,955.96 4157.23,852.73 4439.26,852.73 4663.95,628.04 5367.85,628.04 5627.86,888.05 5627.86,1948.8 5608.16,1968.5 5605.51,1971.16 ccw(c5600.2,1965.85) 5594.9,1971.16 5586.61,1962.87 cw(c5582.01,1967.46) 5577.42,1962.87 5563.63,1976.66 cw(c5568.23,1981.25) 5563.63,1985.85 5590.3,2012.52 ccw(c5585.71,2017.12) 5590.3,2021.71 5576.51,2035.5 ccw(c5571.92,2030.91) 5567.32,2035.5 5540.65,2008.83 cw(c5536.05,2013.43) 5531.46,2008.83 5517.67,2022.62 cw(c5522.26,2027.21) 5517.67,2031.81 5544.34,2058.48 ccw(c5539.74,2063.08) 5544.34,2067.68 5530.55,2081.46 ccw(c5525.96,2076.87) 5521.36,2081.46 5494.69,2054.79 cw(c5490.09,2059.39) 5485.49,2054.79 5471.71,2068.58 cw(c5476.3,2073.18) 5471.71,2077.77 5498.38,2104.45 ccw(c5493.78,2109.04) 5498.38,2113.64 5484.59,2127.43 ccw(c5479.99,2122.83) 5475.4,2127.43 5448.72,2100.75 cw(c5444.13,2105.35) 5439.53,2100.75 5425.74,2114.54 cw(c5430.34,2119.14) 5425.74,2123.73 5452.42,2150.41 ccw(c5447.82,2155) 5452.42,2159.6 5438.63,2173.39 ccw(c5434.03,2168.79) 5429.44,2173.39 5402.76,2146.72 cw(c5398.17,2151.31) 5393.57,2146.72 5379.78,2160.5 cw(c5384.38,2165.1) 5379.78,2169.7 5406.46,2196.37 ccw(c5401.86,2200.97) 5406.45,2205.56 5392.67,2219.35 ccw(c5388.07,2214.75) 5383.47,2219.35 5356.8,2192.68 cw(c5352.21,2197.27) 5347.61,2192.68 5333.82,2206.47 cw(c5338.42,2211.06) 5333.82,2215.66 5360.49,2242.33 ccw(c5355.9,2246.93) 5360.49,2251.52 5346.7,2265.31 ccw(c5342.11,2260.72) 5337.51,2265.31 5313.87,2241.67 cw(c5309.27,2246.26) 5304.67,2241.67 5290.88,2255.45 cw(c5295.48,2260.05) 5290.88,2264.65 5296.15,2269.91 ccw(c5290.84,2275.21) 5296.15,2280.52 5210.53,2366.13 5207.88,2368.78 5179.04,2397.62 5179.04,3779.18 5286.35,3886.49 5361.4,3886.49 5379.09,3904.18 5379.09,3979.53 J501.4@5418.46,4018.9
FT232_RESET: C521.2 R503.1 U501.34 | length 86.1
  L1-Top w6: C521.2@5292.47,3258.67 R503.1@5292.47,3223.63 5294.44,3225.59 U501.34@5342.67,3225.59
FT232_VCCD: C500.2 C503.2 C507.2 C508.2 C509.2 C513.2 C514.2 C515.2 C519.2 C525.2 C527.2 FB500.1 FB501.1 R503.2 R507.2 R510.2 U500.1 U500.5 U501.12 U501.24 U501.39 U501.46 U502.1 U502.5 U503.1 U504.1 U504.5 U505.8 | length 1235.9
  L1-Top w6: v1(5603.5,2869.3) 5603.5,2851.28 5613.04,2841.74 5719.64,2841.74 5745.23,2867.33 R507.2@5745.23,2869.3
  L1-Top w8: v1(5343.26,3562.21) 5344.44,3563.39 5344.44,3614.18 U504.1@5345.62,3615.36 5345.62,3642.92 5383.02,3680.32 U504.5@5383.02,3721.66 ; v1(5391.29,3499.22) 5392.51,3497.99 5392.51,3453.31 U501.24@5392.87,3452.96 ; C513.2@5410.98,3007.09 5410.98,3059.65 5433.61,3082.29 v1(5434.2,3082.29) 5432.59,3083.9 5432.59,3135.68 U501.39@5432.24,3136.03 ; v1(5477.12,3566.15) 5480.27,3569.3 5480.27,3612.21 U500.1@5483.42,3615.36 5483.42,3650.79 5520.82,3688.19 U500.5@5520.82,3721.66 ; U501.46@5570.03,3136.03 5570.38,3135.68 5570.38,3091.78 v1(5572,3090.16) ; v1(5618.46,3566.15) 5619.83,3567.52 5619.83,3613.98 U503.1@5621.21,3615.36 ; U501.12@5659.6,3402.76 5659.68,3402.84 5726.8,3402.84 v1(5728.69,3404.73) ; v1(5756.25,3566.15) 5757.63,3567.52 5757.63,3613.98 U502.1@5759.01,3615.36 5759.01,3646.85 5796.41,3684.26 U502.5@5796.41,3721.66 ; U505.8@5768.85,2998.23 5773.48,3002.86 5821.08,3002.86 5822.79,3004.57 5822.79,3012.6 C527.2@5827.9,3007.48 v1(5827.9,3017.72)
  L1-Top w10: C500.2@5865.17,3293.96 5865.17,3264.51 5875.94,3253.74 v1(5875.94,3247.25) ; C500.2@5865.17,3295.02 5865.17,3324.47 5875.94,3335.24 v1(5875.94,3341.74)
  other v1: 5292.47,3184.26 5865.7,3294.49
FT232_VREGIN: C511.2 C512.2 FB502.1 U501.40 | length 97.1
  L1-Top w8: U501.40@5451.92,3136.03 5451.92,3115.3 5469.64,3097.59 v1(5469.64,3082.29) ; C512.2@5469.05,3082.29 v1(5469.64,3082.29) ; v1(5505.07,3082.29) v1(5469.64,3082.29)
  other v1: 5442.47,3002.37 5481.05,3002.37
FTDI_TCK: U500.3 U501.13 | length 212.2
  L1-Top w7.5: U500.3@5558.22,3615.36 5558.22,3560.24 5568.52,3549.94 5593.14,3549.94 5602.94,3540.15 5626.52,3516.57 5626.52,3486.75 5609.4,3469.63 U501.13@5609.4,3452.96
FTDI_TDI: U501.14 U502.3 | length 360.4
  L1-Top w7.5: U501.14@5589.72,3452.96 5589.72,3489.37 v1(5599.56,3499.22) ; v1(5831.84,3566.15) 5831.84,3613.39 U502.3@5833.81,3615.36
  L4-BOT w7.5: v1(5599.56,3499.22) 5764.91,3499.22 v1(5831.84,3566.15)
FTDI_TDO: U501.15 U503.3 | length 253.3
  L1-Top w7.5: U501.15@5570.03,3452.96 5570.03,3506.17 5578.68,3514.82 v1(5578.68,3516.81) ; v1(5694.05,3566.15) 5694.05,3613.39 U503.3@5696.02,3615.36
  L4-BOT w7.5: v1(5578.68,3516.81) 5594.34,3532.47 5636.58,3532.47 5660.37,3532.47 v1(5694.05,3566.15)
FTDI_TMS: U501.16 U504.3 | length 260
  L1-Top w7.5: U504.3@5420.42,3615.36 5420.42,3548.43 5430.27,3538.59 5449.95,3538.59 5486.9,3501.64 5542.02,3501.64 5550.35,3493.31 U501.16@5550.35,3452.96
GNDADC: C1.2 C2.1 C3.2 J2.7 MC2.16 R6.1 U1.3 | length 2662.2
  L1-Top w7: MC2.16@2515.75,1490.55 2560.17,1490.55 2597.08,1527.47 2659.28,1527.47 v1(2674.76,1542.95)
  L1-Top w10: C1.2@1522.96,2632.55 1522.96,2633.14 1535.37,2645.54 v1(1535.37,2767.8) ; J2.7@1524.88,2925.82 1524.88,2845.84 1535.37,2835.36 v1(1535.37,2767.8) ; R6.1@1792.04,2684.96 1790.07,2684.96 1756.61,2718.43 1690.51,2718.43 1670.44,2738.5 C2.1@1669.84,2738.5 C3.2@1630.62,2738.5 1599.36,2738.5 1570.07,2767.8 v1(1535.37,2767.8)
  L4-BOT w7: v1(1535.37,2767.8) 1474,2706.43 1474,2532.83 1966.64,2040.18 2014.03,2040.18 2038.51,2015.71 2038.51,1987.36 2406.92,1618.95 2598.76,1618.95 v1(2674.76,1542.95)
MGT_REFCLK0_224: J1.1 U8.5 | length 152
  L1-Top w7.5: J1.1@3903.57,706.09 3904.55,706.09 3920.49,722.02 3920.49,723.01 3952.58,755.1 3996.77,755.1 3997.1,755.43 U8.5@4034.51,755.43
MGT_REFCLK0N_224_C: MC3.53 TP31.1 U8.3 | length 1098.4
  L1-Top w5.25: MC3.53@3490.75,1017.72 3490.75,1030.51 3483.87,1037.39 3483.87,1119.91 3522.38,1158.42 3621.2,1158.42 3654.07,1158.42 cw(c3654.07,1152.37) 3660.12,1152.37 3660.12,1151.72 ccw(c3666.17,1151.72) 3666.17,1145.67 3684.32,1145.67 ccw(c3684.32,1151.72) 3690.37,1151.72 3690.37,1152.37 cw(c3696.42,1152.37) 3696.42,1158.42 3722.64,1158.42 3822.92,1158.42 4068.07,913.26 4068.07,813.75 4068.07,718.3 4081.99,704.38 4094.25,704.38 4098.15,700.48 4098.15,672.1 U8.3@4109.31,660.95
MGT_REFCLK0N_225_C: C8.2 MC3.54 | length 1899.7
  L1-Top w7.5: C8.2@2302.25,520.22 2308.74,526.71 2310.79,526.71 2315.18,531.1 2315.18,574.43 2344.78,604.03 2344.78,611.91 v1(2344.3,612.39) ; MC3.54@3490.75,954.72 3490.75,941.93 3485,936.18 3485,911.21 3491.25,904.96 v1(3491.25,901.57)
  L4-BOT w7.5: v1(2344.3,612.39) 2346.69,614.78 2355.53,614.78 2385.01,644.26 2497.55,756.8 2967.05,756.8 3091.13,880.88 3091.13,1106.42 3141.78,1157.07 3440.43,1157.07 3485,1112.5 3485,911.21 3491.25,904.96 v1(3491.25,901.57)
MGT_REFCLK0N_226_C: MC2.4 U3.5 | length 2157.7
  L1-Top w5.25: MC2.4@2515.75,1340.55 2528.54,1340.55 2535.42,1333.68 3734.46,1333.68 4042.46,1025.67 4185.99,882.14 4185.99,722.28 4202.58,705.69 4278.53,705.69 4284.27,699.95 4284.27,697.32 4287.84,693.75 4289.1,693.75 4299.27,683.58 U3.5@4299.27,676.69
MGT_REFCLK0P_224_C: MC3.51 TP30.1 U8.4 | length 1098.8
  L1-Top w5.25: MC3.51@3465.75,1017.72 3465.75,1030.51 3472.62,1037.39 3472.62,1124.57 3517.72,1169.67 3827.58,1169.67 4079.32,917.92 4079.32,722.96 4086.65,715.63 4095.08,715.63 4098.15,718.71 4098.15,744.28 U8.4@4109.31,755.43
MGT_REFCLK0P_225_C: C7.2 MC3.52 | length 1898.6
  L1-Top w7.5: C7.2@2341.62,520.22 2335.13,526.71 2333.08,526.71 2328.68,531.1 2328.68,568.84 2354.33,594.49 2362.2,594.49 v1(2362.69,594.01) ; v1(3465.25,901.57) 3465.25,904.96 3471.5,911.21 3471.5,936.18 3465.75,941.93 MC3.52@3465.75,954.72
  L4-BOT w7.5: v1(2362.69,594.01) 2365.08,596.4 2365.08,605.24 2390.6,630.76 2503.14,743.3 2536.96,743.3 2573.21,743.3 cw(c2573.21,735.8) 2580.71,735.8 2580.71,721.99 ccw(c2587.21,721.99) 2587.21,715.49 2606.71,715.49 ccw(c2606.71,721.99) 2613.21,721.99 2613.21,735.8 cw(c2620.71,735.8) 2620.71,743.3 2649.61,743.3 2972.64,743.3 3104.63,875.29 3104.63,1100.83 3147.37,1143.57 3434.84,1143.57 3471.5,1106.91 3471.5,911.21 3465.25,904.96 v1(3465.25,901.57)
MGT_REFCLK0P_226_C: MC2.2 U3.4 | length 2156.6
  L1-Top w5.25: MC2.2@2515.75,1315.55 2528.54,1315.55 2535.42,1322.43 3729.8,1322.43 4026.55,1025.67 4034.51,1017.72 4174.74,877.48 4174.74,874.3 4174.74,841.43 cw(c4168.69,841.43) 4168.69,835.38 4148.91,835.38 ccw(c4148.91,829.33) 4142.86,829.33 4142.86,811.18 ccw(c4148.91,811.18) 4148.91,805.13 4168.69,805.13 cw(c4168.69,799.08) 4174.74,799.08 4174.74,764.16 4174.74,717.62 4197.92,694.44 4233.86,694.44 4234.54,693.75 4237.92,693.75 U3.4@4254.98,676.69
MGT_RXN0_224: J6.B46 MC3.78 | length 886.9
  L1-Top w7.5: J6.B46@3647.63,137.79 3647.63,206.69 3634.7,219.63 3634.7,251.52 3634.7,698.24 3785,848.54 3785,936.18 3790.75,941.93 MC3.78@3790.75,954.72
MGT_RXN0_225: J6.B28 MC3.48 | length 1064.5
  L1-Top w7.5: J6.B28@2938.97,137.79 2938.97,206.69 2926.03,219.63 2926.03,414.93 3017.82,506.72 3085.08,506.72 3410,831.64 3410,936.18 3415.75,941.93 MC3.48@3415.75,954.72
MGT_RXN0_226: J30.18 MC3.24 | length 1484.9
  L1-Top w5.25: v1(2236.4,827.38) 2237.51,826.27 2247.94,826.27 2282.51,791.7 3000.41,791.7 3108.87,900.16 3108.87,935.05 3115.75,941.93 MC3.24@3115.75,954.72
  L4-BOT w5.25: v1(1919.62,1072.28) 1922.7,1072.28 1930.07,1079.66 2105.38,1079.66 2137.79,1047.24 2145.74,1039.29 2151.57,1033.46 2151.57,922.64 2234.23,839.99 2234.23,829.56 v1(2236.4,827.38)
MGT_RXN1_224: J6.B42 MC3.72 | length 921.1
  L1-Top w7.5: J6.B42@3490.15,137.79 3490.15,206.69 3477.21,219.63 3477.21,251.52 3477.21,625.47 3710,858.25 3710,936.18 3715.75,941.93 MC3.72@3715.75,954.72
MGT_RXN1_225: J6.B24 MC3.42 | length 1139.2
  L1-Top w7.5: J6.B24@2781.49,137.79 2781.49,206.69 2768.55,219.63 2768.55,235.1 2768.55,413.25 2928.41,573.11 3064.84,573.11 3335,843.27 3335,936.18 3340.75,941.93 MC3.42@3340.75,954.72
MGT_RXN1_226: J30.21 MC3.18 | length 1232.2
  L1-Top w5.25: J30.21@2052.5,1086.65 2081.05,1086.65 2085.31,1090.92 2085.31,1093.7 2088.39,1096.78 2197.37,1096.78 2256.74,1037.4 2264.7,1029.45 2280.5,1013.64 2280.5,932.16 2319.52,893.14 2327.48,885.18 2378.44,834.22 2974.36,834.22 3025.92,885.78 3033.87,893.74 3033.87,935.05 3040.75,941.93 MC3.18@3040.75,954.72
MGT_RXN2_224: J6.B38 MC3.66 | length 955.3
  L1-Top w7.5: J6.B38@3332.67,137.79 3332.67,206.69 3319.73,219.63 3319.73,251.52 3319.73,558.21 3635,873.47 3635,936.18 3640.75,941.93 MC3.66@3640.75,954.72
MGT_RXN2_225: J6.B20 MC3.36 | length 1222.3
  L1-Top w7.5: J6.B20@2624.01,137.79 2624.01,206.69 2611.07,219.63 2611.07,235.1 2611.07,427.46 2823.93,640.32 3043.88,640.32 3260,856.44 3260,936.18 3265.75,941.93 MC3.36@3265.75,954.72
MGT_RXN2_226: J30.15 MC3.12 | length 1263.3
  L1-Top w5.25: MC3.12@2965.75,954.72 2965.75,941.93 2958.87,935.05 2958.87,915.41 2966.25,908.03 v1(2966.25,904.96)
  L4-BOT w5.25: v1(1919.62,1166.77) 1922.7,1166.77 1930.07,1174.14 2113.55,1174.14 2427.16,860.53 2938.25,860.53 2958.87,881.15 2958.87,894.51 2966.25,901.88 v1(2966.25,904.96)
MGT_RXN3_224: J6.B34 MC3.60 | length 989.4
  L1-Top w7.5: J6.B34@3175.19,137.79 3175.19,206.69 3162.25,219.63 3162.25,489.46 3560,887.2 3560,936.18 3565.75,941.93 MC3.60@3565.75,954.72
MGT_RXN3_225: J6.B15 MC3.30 | length 1350.4
  L1-Top w7.5: J6.B15@2427.16,137.79 2427.16,206.69 2412.41,221.44 2412.41,436.07 2694.13,717.79 3044.05,717.79 3185,858.75 3185,936.18 3190.75,941.93 MC3.30@3190.75,954.72
MGT_RXN3_226: J30.24 MC3.6 | length 1094.3
  L1-Top w5.25: J30.24@2052.5,1181.14 2081.05,1181.14 2085.31,1185.41 2085.31,1188.19 2088.39,1191.27 2117.25,1191.27 2139.82,1168.69 2143.12,1165.39 2236.05,1165.39 2275.5,1125.94 2283.46,1117.99 2338.11,1063.33 2338.11,972.13 2368.31,941.93 2438.46,871.78 2859.17,871.78 2883.87,896.48 2883.87,935.05 2890.75,941.93 MC3.6@2890.75,954.72
MGT_RXP0_224: J6.B45 MC3.76 | length 886.9
  L1-Top w7.5: J6.B45@3608.26,137.79 3608.26,206.69 3621.2,219.63 3621.2,257.11 3621.2,703.83 3771.5,854.13 3771.5,936.18 3765.75,941.93 MC3.76@3765.75,954.72
MGT_RXP0_225: J6.B27 MC3.46 | length 1064.5
  L1-Top w7.5: J6.B27@2899.6,137.79 2899.6,206.69 2912.53,219.63 2912.53,420.52 3012.23,520.22 3079.49,520.22 3396.5,837.23 3396.5,936.18 3390.75,941.93 MC3.46@3390.75,954.72
MGT_RXP0_226: J30.17 MC3.22 | length 1484.7
  L1-Top w5.25: v1(2254.78,845.77) 2255.9,844.65 2255.9,834.22 2287.17,802.95 2995.75,802.95 3097.62,904.82 3097.62,935.05 3090.75,941.93 MC3.22@3090.75,954.72
  L4-BOT w5.25: v1(1919.62,1098.28) 1922.7,1098.28 1930.07,1090.91 2110.04,1090.91 2145.74,1055.2 2162.82,1038.12 2162.82,927.3 2182.06,908.06 2183.91,906.21 ccw(c2188.19,910.48) 2192.47,906.21 2194.1,907.83 cw(c2198.38,903.56) 2202.65,907.83 2215.49,895 cw(c2211.21,890.72) 2215.49,886.44 2213.86,884.82 ccw(c2218.14,880.54) 2213.86,876.26 2223.73,866.39 2225.59,864.53 2242.18,847.94 2252.61,847.94 v1(2254.78,845.77)
MGT_RXP1_224: J6.B41 MC3.70 | length 921.1
  L1-Top w7.5: J6.B41@3450.78,137.79 3450.78,206.69 3463.71,219.63 3463.71,257.11 3463.71,631.06 3696.5,863.85 3696.5,936.18 3690.75,941.93 MC3.70@3690.75,954.72
MGT_RXP1_225: J6.B23 MC3.40 | length 1139.2
  L1-Top w7.5: J6.B23@2742.12,137.79 2742.12,206.69 2755.05,219.63 2755.05,240.7 2755.05,418.85 2922.82,586.61 3059.25,586.61 3321.5,848.87 3321.5,936.18 3315.75,941.93 MC3.40@3315.75,954.72
MGT_RXP1_226: J30.22 MC3.16 | length 1232.2
  L1-Top w5.25: J30.22@2052.5,1118.15 2081.05,1118.15 2085.31,1113.89 2085.31,1111.1 2088.39,1108.03 2202.03,1108.03 2264.7,1045.36 2291.75,1018.3 2291.75,936.82 2321.33,907.24 2323.19,905.38 ccw(c2327.47,909.66) 2331.74,905.38 2333.45,907.09 cw(c2337.73,902.81) 2342.01,907.09 2354.84,894.25 cw(c2350.56,889.97) 2354.84,885.7 2353.13,883.99 ccw(c2357.41,879.71) 2353.13,875.43 2370.98,857.59 2372.83,855.74 2383.1,845.47 2969.7,845.47 3022.62,898.4 3022.62,935.05 3015.75,941.93 MC3.16@3015.75,954.72
MGT_RXP2_224: J6.B37 MC3.64 | length 955.3
  L1-Top w7.5: J6.B37@3293.3,137.79 3293.3,206.69 3306.23,219.63 3306.23,257.11 3306.23,563.8 3621.5,879.06 3621.5,936.18 3615.75,941.93 MC3.64@3615.75,954.72
MGT_RXP2_225: J6.B19 MC3.34 | length 1222.3
  L1-Top w7.5: J6.B19@2584.64,137.79 2584.64,206.69 2597.57,219.63 2597.57,240.7 2597.57,433.05 2818.34,653.82 3038.29,653.82 3246.5,862.03 3246.5,936.18 3240.75,941.93 MC3.34@3240.75,954.72
MGT_RXP2_226: J30.14 MC3.10 | length 1263.1
  L1-Top w5.25: v1(2940.25,904.96) 2940.25,908.03 2947.62,915.41 2947.62,935.05 2940.75,941.93 MC3.10@2940.75,954.72
  L4-BOT w5.25: v1(1919.62,1192.77) 1922.7,1192.77 1930.07,1185.39 2118.21,1185.39 2431.82,871.78 2693.06,871.78 2695.69,871.78 ccw(c2695.69,877.83) 2701.74,877.83 2701.74,880.13 cw(c2707.79,880.13) 2707.79,886.18 2725.94,886.18 cw(c2725.94,880.13) 2731.99,880.13 2731.99,877.83 ccw(c2738.04,877.83) 2738.04,871.78 2785.53,871.78 2933.59,871.78 2947.62,885.81 2947.62,894.51 2940.25,901.88 v1(2940.25,904.96)
MGT_RXP3_224: J6.B33 MC3.58 | length 989.4
  L1-Top w7.5: J6.B33@3135.82,137.79 3135.82,206.69 3148.75,219.63 3148.75,495.05 3546.5,892.8 3546.5,936.18 3540.75,941.93 MC3.58@3540.75,954.72
MGT_RXP3_225: J6.B14 MC3.28 | length 1348.9
  L1-Top w7.5: J6.B14@2387.79,137.79 2387.79,206.69 2398.91,217.81 2398.91,441.66 2688.54,731.29 3038.45,731.29 3171.5,864.34 3171.5,936.18 3165.75,941.93 MC3.28@3165.75,954.72
MGT_RXP3_226: J30.25 MC3.4 | length 1094.3
  L1-Top w5.25: J30.25@2052.5,1212.64 2081.05,1212.64 2085.31,1208.37 2085.31,1205.59 2088.39,1202.52 2121.91,1202.52 2147.78,1176.64 2240.71,1176.64 2283.46,1133.9 2349.36,1067.99 2349.36,976.79 2443.12,883.03 2619.43,883.03 2622.06,883.03 ccw(c2622.06,889.08) 2628.11,889.08 2628.11,891.49 cw(c2634.16,891.49) 2634.16,897.54 2652.31,897.54 cw(c2652.31,891.49) 2658.36,891.49 2658.36,889.08 ccw(c2664.41,889.08) 2664.41,883.03 2688.54,883.03 2854.51,883.03 2872.62,901.14 2872.62,935.05 2865.75,941.93 MC3.4@2865.75,954.72
MGT_TXN0_224: C30.2 MC3.77 | length 814.9
  L1-Top w7.5: v1(3720.46,391.89) 3720.46,388.51 3713.44,381.48 3713.44,369.54 3717.83,365.15 3719.88,365.15 C30.2@3726.37,358.66 ; MC3.77@3790.75,1017.72 3790.75,1030.51 3785,1036.26 3785,1061.23 3791.25,1067.48 v1(3791.25,1070.87)
  L4-BOT w7.5: v1(3720.46,391.89) 3720.46,395.27 3713.44,402.3 3713.44,734.54 3785,806.1 3785,1061.23 3791.25,1067.48 v1(3791.25,1070.87)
